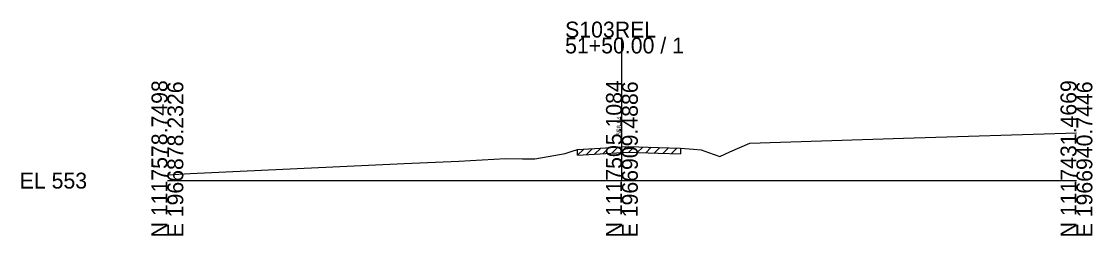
# Model space of a CAD drawing. Extents: x -26 to 163, y -10 to 24518.
# Drawn here: x -25.7 to 162.8, y 1990.3 to 2028.1 of the extents above; entities that cross this region are included whole.
import ezdxf

# ---------------------------------------------------------------- set-up
doc = ezdxf.new("R2010")
doc.units = 0
for name, color, linetype in [('RD_GPK_XS_Cell', 7, 'Continuous'), ('RD_XS_ExGround', 7, 'Continuous'), ('RD_XS_ExPaveRet', 7, 'Continuous'), ('RD_XS_TX_Elev_EX', 7, 'Continuous')]:
    doc.layers.add(name, color=color, linetype=linetype)

msp = doc.modelspace()

# ---------------------------------------------------------------- linework, layer by layer
at = {"layer": 'RD_GPK_XS_Cell'}
for p, q in [((80, 2000), (80, 2025.22)), ((0, 2000), (80, 2000)), ((80, 2000), (160, 2000))]:
    msp.add_line(p, q, dxfattribs=at)
at = {"layer": 'RD_XS_ExGround'}
msp.add_lwpolyline([(0, 2001.02), (3.99, 2001.28), (41.7, 2002.99), (51.31, 2003.44), (59.51, 2003.89), (62.49, 2003.83), (64.65, 2003.81), (67.02, 2004.23), (70.04, 2004.76), (71.27, 2005.21), (72.2, 2005.47), (76.16, 2005.71), (80, 2005.94), (81.15, 2006), (86.39, 2005.83), (90.3, 2005.7), (92.6, 2005.52), (93.92, 2005.42), (95.23, 2004.96), (97.21, 2004.23), (98.98, 2005.05), (102.51, 2006.62), (129.56, 2007.46), (160, 2008.41)], dxfattribs=at)
at = {"layer": 'RD_XS_ExPaveRet'}
for p, q in [((72.2, 2004.47), (73.27, 2005.54)), ((72.2, 2004.47), (72.2, 2005.47)), ((72.2, 2004.47), (76.16, 2004.71)), ((73.7, 2004.56), (74.77, 2005.63)), ((75.2, 2004.66), (76.27, 2005.72)), ((76.16, 2004.71), (80, 2004.94)), ((76.7, 2004.75), (77.76, 2005.81)), ((78.2, 2004.83), (79.26, 2005.89)), ((79.7, 2004.92), (80.76, 2005.98)), ((80, 2004.94), (81.15, 2005)), ((81.15, 2005), (86.39, 2004.83)), ((81.2, 2005), (82.17, 2005.97)), ((82.7, 2004.95), (83.67, 2005.92)), ((84.2, 2004.9), (85.17, 2005.87)), ((85.7, 2004.85), (86.67, 2005.82)), ((86.39, 2004.83), (90.3, 2004.7)), ((87.2, 2004.8), (88.17, 2005.77)), ((88.7, 2004.75), (89.67, 2005.72)), ((90.3, 2005.7), (90.3, 2004.7))]:
    msp.add_line(p, q, dxfattribs=at)

# ---------------------------------------------------------------- texts
at = {"layer": 'RD_GPK_XS_Cell'}
for s, p in [('S103REL', (70, 2025.22)), ('51+50.00 / 1', (70, 2022.42)), ('EL 553', (-26, 1998.6))]:
    msp.add_text(s, height=2.8, dxfattribs=at).set_placement(p)
for s, p in [('N 1117578.7498', (0, 1990)), ('E 1966878.2326', (2.8, 1990)), ('N 1117505.1084', (80, 1990)), ('E 1966909.4886', (82.8, 1990)), ('N 1117431.4669', (160, 1990)), ('E 1966940.7446', (162.8, 1990))]:
    msp.add_text(s, height=2.8, rotation=90, dxfattribs=at).set_placement(p)
at = {"layer": 'RD_XS_TX_Elev_EX'}
msp.add_text('558.94', height=0.8, rotation=90, dxfattribs=at).set_placement((79.9, 2007.94))

doc.saveas('drawing.dxf')
